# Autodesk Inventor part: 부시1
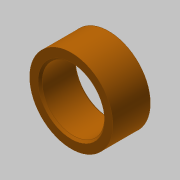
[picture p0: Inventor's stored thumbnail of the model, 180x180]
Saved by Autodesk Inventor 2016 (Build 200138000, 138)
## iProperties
Created: 2016-08
Part Number: 부시1
Material: 강철, 탄소
Document SubType Name: Modeling
Designer: mduedu
Density: 7.87 g/cm^3
Appearance: 주황색
Author: mduedu
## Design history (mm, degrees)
sketch "스케치1"
  geometry: C1 r 7.5 at (0, 0); C2 r 10 at (0, 0); 1 further point
  constraints: 2 centre point, 2 coincident
  dimensions: "d0" = 15 diameter of C1; "d1" = 20 diameter of C2
extrude "돌출1" new body sketch "스케치1" stored distance "d2" = 9; taper "d3" = 0 deg
chamfer "모따기1" distance "d4" = 0.5; stored, may be unused: second distance "d5" = 2, angle "d6" = 45 deg
node "솔리드1"
